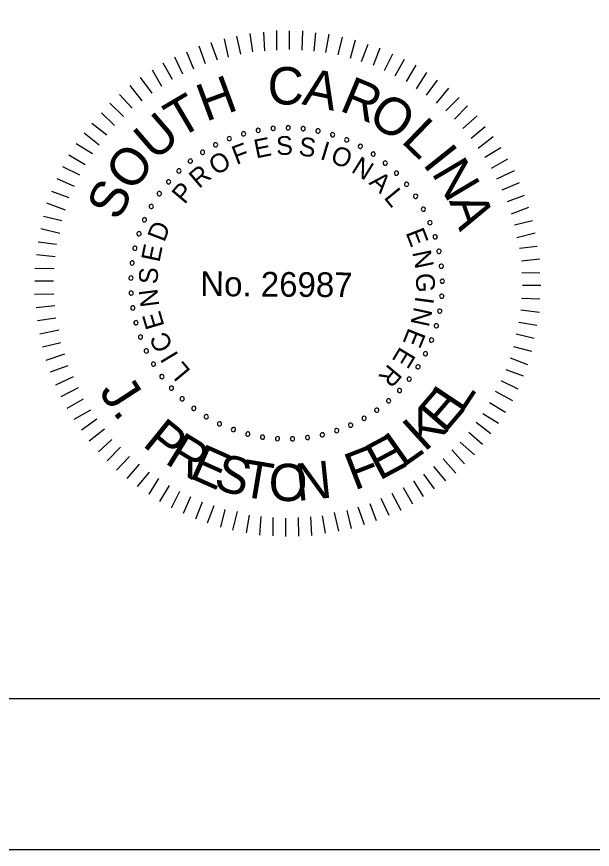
# Model space of a CAD drawing. Extents: x -125.5 to -89.4, y -5.1 to 16.9.
# Drawn here: x -102.12 to -100.213, y -5.066 to -2.306 of the extents above; entities that cross this region are included whole.
import ezdxf

# ---------------------------------------------------------------- set-up
doc = ezdxf.new("R2010")
doc.units = 0
for name, color, linetype in [('BR_BORDER LINES', 7, 'Continuous'), ('BR_TEXT', 7, 'Continuous'), ('Level 31', 7, 'Continuous')]:
    doc.layers.add(name, color=color, linetype=linetype)

msp = doc.modelspace()

# ---------------------------------------------------------------- linework, layer by layer
at = {"layer": 'BR_BORDER LINES'}
msp.add_line((-123.6994, -4.5662), (-90.0334, -4.5662), dxfattribs=at)
at = {"layer": 'BR_TEXT'}
for p, q in [((-101.3767, -2.4304), (-101.3908, -2.3711)), ((-101.3372, -2.423), (-101.3461, -2.362)), ((-101.2977, -2.419), (-101.3015, -2.3581)), ((-101.2582, -2.4168), (-101.2576, -2.3524)), ((-101.2161, -2.4146), (-101.2156, -2.3528)), ((-101.1741, -2.4175), (-101.1718, -2.3531)), ((-101.1338, -2.4204), (-101.129, -2.3595)), ((-101.0952, -2.425), (-101.0844, -2.3642)), ((-101.4541, -2.4504), (-101.476, -2.3927)), ((-101.418, -2.4404), (-101.4312, -2.3793)), ((-101.0549, -2.4331), (-101.0407, -2.374)), ((-101.0138, -2.4437), (-100.9979, -2.3829)), ((-100.977, -2.4543), (-100.9551, -2.397)), ((-101.5325, -2.4798), (-101.556, -2.4238)), ((-101.4937, -2.4629), (-101.5147, -2.4044)), ((-100.9376, -2.4675), (-100.9157, -2.4093)), ((-101.5695, -2.4966), (-101.5957, -2.4406)), ((-100.9017, -2.485), (-100.8738, -2.4294)), ((-100.8658, -2.5024), (-100.8345, -2.4469)), ((-101.6394, -2.5381), (-101.6698, -2.4838)), ((-101.604, -2.5144), (-101.6344, -2.46)), ((-100.8282, -2.5208), (-100.796, -2.467)), ((-101.6704, -2.5593), (-101.7095, -2.5083)), ((-100.795, -2.5451), (-100.761, -2.4913)), ((-101.7041, -2.5847), (-101.744, -2.5346)), ((-100.7617, -2.5668), (-100.7252, -2.5165)), ((-101.7369, -2.6094), (-101.7786, -2.5644)), ((-100.7293, -2.5928), (-100.6886, -2.5434)), ((-101.7663, -2.6366), (-101.8106, -2.5925)), ((-100.6977, -2.618), (-100.6545, -2.5737)), ((-100.6697, -2.6456), (-100.6264, -2.6022)), ((-101.7958, -2.6673), (-101.8392, -2.6248)), ((-100.6416, -2.6768), (-100.594, -2.6351)), ((-101.8209, -2.6988), (-101.8704, -2.6598)), ((-100.6144, -2.7088), (-100.5677, -2.6705)), ((-101.8469, -2.732), (-101.8964, -2.6922)), ((-100.5906, -2.7424), (-100.5414, -2.7033)), ((-101.8686, -2.761), (-101.9224, -2.728)), ((-100.5686, -2.7718), (-100.516, -2.7396)), ((-101.893, -2.7977), (-101.9467, -2.7656)), ((-100.5466, -2.8089), (-100.4931, -2.7776)), ((-101.9104, -2.8319), (-101.9668, -2.804)), ((-100.5288, -2.8433), (-100.4711, -2.8164)), ((-101.9279, -2.8687), (-101.9852, -2.8433)), ((-100.5111, -2.8804), (-100.4543, -2.856)), ((-101.9454, -2.9072), (-102.0035, -2.8852)), ((-101.9577, -2.9474), (-102.0193, -2.9246)), ((-100.4943, -2.9192), (-100.4374, -2.8982)), ((-100.4809, -2.9596), (-100.4232, -2.9378)), ((-101.97, -2.9833), (-102.0308, -2.9682)), ((-100.4708, -2.9957), (-100.4107, -2.9816)), ((-101.9772, -3.0253), (-102.0397, -3.0094)), ((-100.4626, -3.0378), (-100.4024, -3.0229)), ((-101.9878, -3.0613), (-102.0487, -3.0531)), ((-100.4543, -3.074), (-100.3951, -3.0667)), ((-101.9925, -3.1024), (-102.0542, -3.0951)), ((-100.4478, -3.1152), (-100.3868, -3.1088)), ((-101.9954, -3.1419), (-102.0597, -3.1414)), ((-100.4464, -3.1547), (-100.3863, -3.1552)), ((-101.9974, -3.183), (-102.06, -3.1825)), ((-100.4442, -3.1959), (-100.3833, -3.1964)), ((-101.9961, -3.226), (-102.0604, -3.2272)), ((-100.4471, -3.2388), (-100.3871, -3.241)), ((-101.9938, -3.2646), (-102.0556, -3.2718)), ((-100.4492, -3.2774), (-100.3883, -3.2856)), ((-101.9898, -3.3058), (-102.0509, -3.3148)), ((-100.4564, -3.3185), (-100.3972, -3.3284)), ((-101.9799, -3.3454), (-102.0426, -3.3586)), ((-100.4653, -3.3579), (-100.4053, -3.3721)), ((-101.9733, -3.3875), (-102.0344, -3.4016)), ((-100.4742, -3.3999), (-100.4143, -3.415)), ((-101.9616, -3.4245), (-102.0236, -3.4454)), ((-100.4848, -3.4367), (-100.4275, -3.4586)), ((-101.95, -3.4632), (-102.0085, -3.4842)), ((-100.4989, -3.4752), (-100.4424, -3.4971)), ((-101.9331, -3.5003), (-101.9908, -3.5272)), ((-100.5163, -3.512), (-100.4599, -3.5399)), ((-101.9162, -3.5364), (-101.9731, -3.566)), ((-100.5346, -3.5479), (-100.4774, -3.5784)), ((-101.8994, -3.5735), (-101.9537, -3.6048)), ((-100.553, -3.5846), (-100.5, -3.6168)), ((-101.8756, -3.6106), (-101.93, -3.6419)), ((-101.8544, -3.6399), (-101.9045, -3.6764)), ((-100.5756, -3.6213), (-100.5235, -3.6535)), ((-100.5981, -3.6503), (-100.5495, -3.6876)), ((-101.829, -3.6736), (-101.8791, -3.7127)), ((-100.6224, -3.6836), (-100.5764, -3.7234)), ((-101.8043, -3.7073), (-101.8485, -3.7481)), ((-100.6502, -3.7168), (-100.6033, -3.7584)), ((-101.7754, -3.7333), (-101.8204, -3.7784)), ((-100.6787, -3.7423), (-100.6362, -3.7882)), ((-101.7465, -3.7636), (-101.7889, -3.8095)), ((-100.7073, -3.7721), (-100.6648, -3.8188)), ((-101.714, -3.7895), (-101.7548, -3.8364)), ((-100.7392, -3.7976), (-100.6993, -3.8452)), ((-101.6808, -3.8156), (-101.7207, -3.8633)), ((-100.772, -3.8231), (-100.7364, -3.8714)), ((-101.6501, -3.8373), (-101.6814, -3.8894)), ((-101.6151, -3.8599), (-101.6464, -3.9137)), ((-100.8057, -3.8443), (-100.7727, -3.8969)), ((-101.5809, -3.8799), (-101.608, -3.9355)), ((-100.8773, -3.8857), (-100.8468, -3.9418)), ((-100.8393, -3.8663), (-100.808, -3.9206)), ((-101.5442, -3.8974), (-101.5687, -3.953)), ((-101.5057, -3.9149), (-101.5276, -3.9713)), ((-100.9135, -3.9026), (-100.8865, -3.9586)), ((-101.4663, -3.9272), (-101.4891, -3.9854)), ((-101.4304, -3.9395), (-101.4446, -3.9986)), ((-101.3892, -3.9467), (-101.4044, -4.0084)), ((-101.0262, -3.9429), (-101.0112, -4.0022)), ((-100.9892, -3.9311), (-100.9682, -3.9897)), ((-100.9496, -3.9194), (-100.9286, -3.9763)), ((-101.3499, -3.9582), (-101.3598, -4.0165)), ((-101.3104, -3.9628), (-101.3152, -4.0246)), ((-101.271, -3.9657), (-101.2715, -4.0275)), ((-101.229, -3.9686), (-101.2295, -4.0296)), ((-101.1869, -3.9664), (-101.1857, -4.0282)), ((-101.1466, -3.9642), (-101.1428, -4.026)), ((-101.1079, -3.9602), (-101.098, -4.0186)), ((-101.0675, -3.9494), (-101.0542, -4.0113))]:
    msp.add_line(p, q, dxfattribs=at)
for centre, start, end in [((-101.3196, -2.6831), 10.6038, 190.6038), ((-101.2702, -2.6764), 5.0653, 185.0653), ((-101.2702, -2.6764), 185.0653, 5.0653), ((-101.2204, -2.6745), 359.5268, 179.5268), ((-101.2204, -2.6745), 179.5268, 359.5268), ((-101.1707, -2.6774), 173.9884, 353.9884), ((-101.1707, -2.6774), 353.9884, 173.9884), ((-101.4153, -2.7106), 21.6807, 201.6807), ((-101.3681, -2.6945), 16.1422, 196.1422), ((-101.3681, -2.6945), 196.1422, 16.1422), ((-101.3196, -2.6831), 190.6038, 10.6038), ((-101.1214, -2.6851), 168.4499, 348.4499), ((-101.1214, -2.6851), 348.4499, 168.4499), ((-101.0732, -2.6976), 162.9114, 342.9114), ((-101.0732, -2.6976), 342.9114, 162.9114), ((-101.4607, -2.7311), 27.2191, 207.2191), ((-101.4607, -2.7311), 207.2191, 27.2191), ((-101.4153, -2.7106), 201.6807, 21.6807), ((-101.0263, -2.7146), 157.373, 337.373), ((-101.0263, -2.7146), 337.373, 157.373), ((-100.9814, -2.736), 331.8345, 151.8345), ((-101.5039, -2.7559), 32.7576, 212.7576), ((-101.5039, -2.7559), 212.7576, 32.7576), ((-100.9814, -2.736), 151.8345, 331.8345), ((-100.9387, -2.7617), 146.2961, 326.2961), ((-100.9387, -2.7617), 326.2961, 146.2961), ((-101.5445, -2.7848), 38.2961, 218.2961), ((-101.5445, -2.7848), 218.2961, 38.2961), ((-100.8987, -2.7914), 140.7576, 320.7576), ((-100.8987, -2.7914), 320.7576, 140.7576), ((-101.5821, -2.8175), 43.8345, 223.8345), ((-101.5821, -2.8175), 223.8345, 43.8345), ((-100.8617, -2.8249), 135.2191, 315.2191), ((-100.8617, -2.8249), 315.2191, 135.2191), ((-101.6164, -2.8536), 49.373, 229.373), ((-101.6164, -2.8536), 229.373, 49.373), ((-100.8282, -2.8617), 129.6807, 309.6807), ((-100.8282, -2.8617), 309.6807, 129.6807), ((-101.6471, -2.8929), 54.9114, 234.9114), ((-101.6471, -2.8929), 234.9114, 54.9114), ((-100.7983, -2.9016), 124.1422, 304.1422), ((-100.7983, -2.9016), 304.1422, 124.1422), ((-101.6738, -2.935), 60.4499, 240.4499), ((-101.6738, -2.935), 240.4499, 60.4499), ((-100.7724, -2.9442), 118.6038, 298.6038), ((-100.7724, -2.9442), 298.6038, 118.6038), ((-101.6964, -2.9794), 65.9884, 245.9884), ((-101.6964, -2.9794), 245.9884, 65.9884), ((-100.7508, -2.9891), 113.0653, 293.0653), ((-100.7508, -2.9891), 293.0653, 113.0653), ((-101.7145, -3.0258), 71.5268, 251.5268), ((-101.7145, -3.0258), 251.5268, 71.5268), ((-100.7336, -3.0359), 107.5268, 287.5268), ((-100.7336, -3.0359), 287.5268, 107.5268), ((-101.7281, -3.0738), 77.0653, 257.0653), ((-101.7281, -3.0738), 257.0653, 77.0653), ((-100.721, -3.0841), 101.9884, 281.9884), ((-100.721, -3.0841), 281.9884, 101.9884), ((-101.737, -3.1228), 82.6038, 262.6038), ((-101.737, -3.1228), 262.6038, 82.6038), ((-100.7131, -3.1333), 96.4499, 276.4499), ((-100.7131, -3.1333), 276.4499, 96.4499), ((-101.7411, -3.1724), 88.1422, 268.1422), ((-101.7411, -3.1724), 268.1422, 88.1422), ((-100.71, -3.183), 90.9114, 270.9114), ((-100.71, -3.183), 270.9114, 90.9114), ((-101.7404, -3.2223), 93.6807, 273.6807), ((-101.7404, -3.2223), 273.6807, 93.6807), ((-100.7118, -3.2328), 85.373, 265.373), ((-100.7118, -3.2328), 265.373, 85.373), ((-101.7349, -3.2718), 99.2191, 279.2191), ((-101.7349, -3.2718), 279.2191, 99.2191), ((-100.7183, -3.2822), 79.8345, 259.8345), ((-100.7183, -3.2822), 259.8345, 79.8345), ((-101.7246, -3.3206), 104.7576, 284.7576), ((-101.7246, -3.3206), 284.7576, 104.7576), ((-100.7295, -3.3308), 74.2961, 254.2961), ((-100.7295, -3.3308), 254.2961, 74.2961), ((-101.7097, -3.3681), 110.2961, 290.2961), ((-101.7097, -3.3681), 290.2961, 110.2961), ((-100.7454, -3.378), 68.7576, 248.7576), ((-100.7454, -3.378), 248.7576, 68.7576), ((-101.6903, -3.414), 115.8345, 295.8345), ((-101.6903, -3.414), 295.8345, 115.8345), ((-100.7658, -3.4235), 63.2191, 243.2191), ((-100.7658, -3.4235), 243.2191, 63.2191), ((-101.6665, -3.4578), 121.373, 301.373), ((-101.6665, -3.4578), 301.373, 121.373), ((-100.7904, -3.4668), 57.6807, 237.6807), ((-100.7904, -3.4668), 237.6807, 57.6807), ((-101.6386, -3.4991), 126.9114, 306.9114), ((-101.6386, -3.4991), 306.9114, 126.9114), ((-100.8192, -3.5075), 52.1422, 232.1422), ((-100.8192, -3.5075), 232.1422, 52.1422), ((-101.6069, -3.5375), 132.4499, 312.4499), ((-101.6069, -3.5375), 312.4499, 132.4499), ((-100.8517, -3.5452), 46.6038, 226.6038), ((-100.8517, -3.5452), 226.6038, 46.6038), ((-101.5716, -3.5727), 137.9884, 317.9884), ((-101.5716, -3.5727), 317.9884, 137.9884), ((-100.8877, -3.5797), 41.0653, 221.0653), ((-100.8877, -3.5797), 221.0653, 41.0653), ((-101.5331, -3.6043), 143.5268, 323.5268), ((-101.5331, -3.6043), 323.5268, 143.5268), ((-100.9269, -3.6105), 35.5268, 215.5268), ((-100.9269, -3.6105), 215.5268, 35.5268), ((-101.4917, -3.632), 149.0653, 329.0653), ((-101.4917, -3.632), 329.0653, 149.0653), ((-100.9688, -3.6374), 29.9884, 209.9884), ((-100.9688, -3.6374), 209.9884, 29.9884), ((-101.4478, -3.6556), 154.6038, 334.6038), ((-101.4478, -3.6556), 334.6038, 154.6038), ((-101.4018, -3.6749), 340.1422, 160.1422), ((-101.0132, -3.6601), 24.4499, 204.4499), ((-101.0132, -3.6601), 204.4499, 24.4499), ((-101.4018, -3.6749), 160.1422, 340.1422), ((-101.3542, -3.6896), 165.6807, 345.6807), ((-101.3542, -3.6896), 345.6807, 165.6807), ((-101.3054, -3.6997), 351.2191, 171.2191), ((-101.2559, -3.705), 356.7576, 176.7576), ((-101.1564, -3.7012), 7.8345, 187.8345), ((-101.1074, -3.6921), 13.373, 193.373), ((-101.1074, -3.6921), 193.373, 13.373), ((-101.0595, -3.6784), 18.9114, 198.9114), ((-101.0595, -3.6784), 198.9114, 18.9114), ((-101.3054, -3.6997), 171.2191, 351.2191), ((-101.2559, -3.705), 176.7576, 356.7576), ((-101.2061, -3.7055), 2.2961, 182.2961), ((-101.2061, -3.7055), 182.2961, 2.2961), ((-101.1564, -3.7012), 187.8345, 7.8345)]:
    msp.add_arc(centre, 0.00701, start, end, dxfattribs=at)
at = {"layer": 'Level 31'}
msp.add_lwpolyline([(-125.5328, 16.9339), (-125.5328, -5.0661), (-89.5328, -5.0661), (-89.5328, 16.9339)], dxfattribs=at)

# ---------------------------------------------------------------- texts
at = {"layer": 'BR_TEXT'}
for s, height, rotation, p in [('C', 0.1241, 359.5482, (-101.2889, -2.5969)), ('H', 0.1241, 20.3637, (-101.4933, -2.6552)), ('A', 0.1241, 348.1981, (-101.1775, -2.5961)), ('R', 0.1241, 337.4344, (-101.0542, -2.616)), ('T', 0.1241, 30.4992, (-101.5812, -2.7128)), ('O', 0.1239, 326.5869, (-100.962, -2.6528)), ('U', 0.1241, 40.8022, (-101.6624, -2.7875)), ('L', 0.1241, 315.9488, (-100.8494, -2.7205)), ('S', 0.0622, 2.208, (-101.2591, -2.7654)), ('F', 0.0622, 20.6127, (-101.392, -2.7981)), ('E', 0.0622, 11.4103, (-101.3269, -2.7764)), ('S', 0.0622, 352.6608, (-101.1878, -2.7657)), ('I', 0.0622, 343.1136, (-101.1175, -2.7777)), ('I', 0.1241, 308.6613, (-100.778, -2.7948)), ('O', 0.1241, 52.0267, (-101.7369, -2.8914)), ('O', 0.0622, 30.8477, (-101.4594, -2.8341)), ('O', 0.0622, 338.4392, (-101.0841, -2.7878)), ('N', 0.0622, 328.2042, (-101.0145, -2.8192)), ('N', 0.1241, 300.7037, (-100.7474, -2.8242)), ('R', 0.0622, 40.3949, (-101.5156, -2.878)), ('A', 0.0622, 318.657, (-100.9555, -2.8592)), ('S', 0.1239, 63.2511, (-101.7823, -2.9871)), ('P', 0.0622, 49.9421, (-101.5636, -2.9306)), ('L', 0.0622, 309.4546, (-100.9057, -2.9066)), ('A', 0.1241, 289.4792, (-100.6882, -2.9172)), ('D', 0.0622, 69.0364, (-101.6306, -3.0559)), ('E', 0.0622, 291.049, (-100.8319, -3.0219)), ('E', 0.0622, 78.2388, (-101.6472, -3.1226)), ('N', 0.0622, 281.8466, (-100.8097, -3.0869)), ('S', 0.0622, 87.786, (-101.6529, -3.1936)), ('No. 26987', 0.08175, 359.5268, (-101.5118, -3.232)), ('G', 0.0622, 272.2995, (-100.7979, -3.1572)), ('N', 0.0622, 97.3332, (-101.6467, -3.2646)), ('I', 0.0622, 262.4084, (-100.7983, -3.231)), ('E', 0.0622, 106.5355, (-101.6297, -3.3312)), ('N', 0.0622, 257.7339, (-100.8028, -3.2656)), ('C', 0.0622, 116.4266, (-101.5998, -3.3987)), ('E', 0.0622, 248.1867, (-100.8209, -3.3346)), ('I', 0.0622, 121.1011, (-101.5818, -3.4285)), ('E', 0.0622, 238.9844, (-100.8488, -3.3973)), ('L', 0.0622, 129.9595, (-101.5411, -3.4807)), ('R', 0.0622, 229.782, (-100.8865, -3.4548)), ('J', 0.1236, 302.9559, (-101.849, -3.5492)), ('L', 0.1236, 56.4247, (-100.6455, -3.6233)), ('E', 0.1236, 49.3639, (-100.703, -3.6911)), ('K', 0.1236, 42.3031, (-100.7683, -3.7512)), ('.', 0.1236, 309.3974, (-101.8049, -3.6172)), ('P', 0.1236, 321.1035, (-101.7065, -3.7264)), ('R', 0.1236, 328.5359, (-101.6332, -3.7844)), ('E', 0.1236, 28.1814, (-100.9186, -3.8452)), ('L', 0.1236, 35.2422, (-100.8406, -3.8028)), ('E', 0.1236, 335.9684, (-101.5531, -3.8325)), ('F', 0.1236, 21.1206, (-101.0013, -3.8776)), ('S', 0.1236, 343.0292, (-101.4718, -3.8682)), ('T', 0.1236, 350.4617, (-101.3821, -3.8947)), ('N', 0.1236, 5.8221, (-101.1902, -3.9118)), ('O', 0.1236, 358.1419, (-101.2867, -3.9097))]:
    msp.add_text(s, height=height, rotation=rotation, dxfattribs=at).set_placement(p)

doc.saveas('drawing.dxf')
